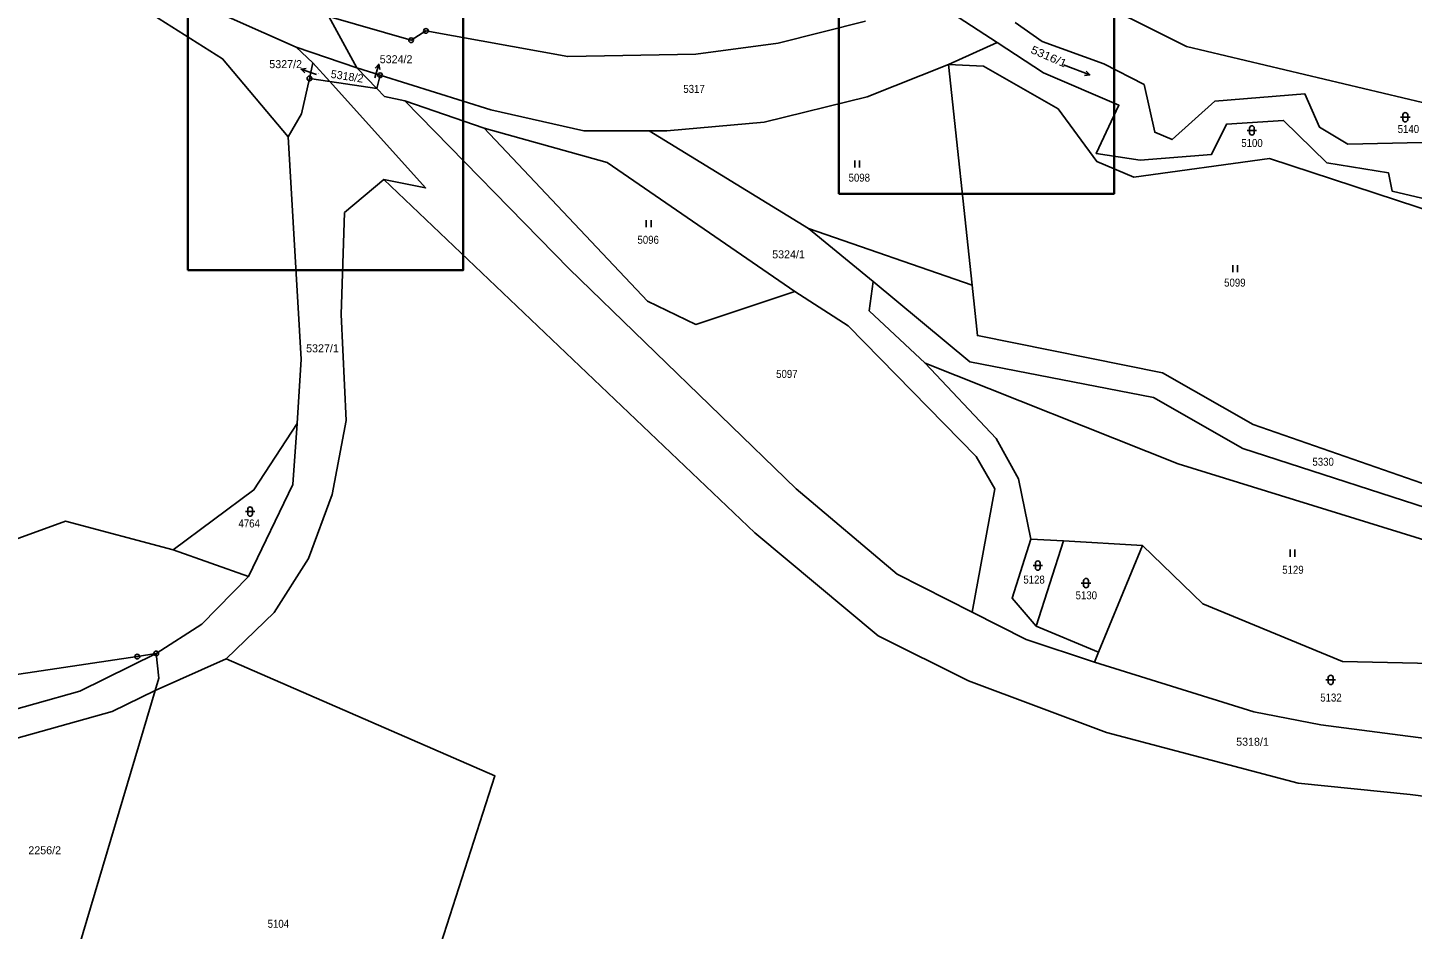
# Model space of a CAD drawing. Extents: x -665688 to -664583, y -1006118 to -1004927.
# Drawn here: x -665191.6 to -664897.5, y -1005645.6 to -1005454.1 of the extents above; entities that cross this region are included whole.
import ezdxf
from ezdxf.enums import TextEntityAlignment as Align

# ---------------------------------------------------------------- set-up
doc = ezdxf.new("R2010")
doc.units = 0
doc.header["$LTSCALE"] = 0.68
for name, color, linetype, lineweight in [('1', 7, 'Continuous', 25), ('13', 7, 'Continuous', 25), ('16', 7, 'Continuous', 25), ('24', 7, 'Continuous', 25), ('25', 7, 'Continuous', 25), ('55', 7, 'Continuous', 35)]:
    doc.layers.add(name, color=color, linetype=linetype, lineweight=lineweight)
doc.layers.add('18', color=7, linetype='Continuous')

msp = doc.modelspace()

# ---------------------------------------------------------------- linework, layer by layer
at = {"layer": '1'}
for p, q in [((-665000.67, -1005447.45), (-664985.67, -1005457.24)), ((-665094.68, -1005475.42), (-665111.5, -1005469.59)), ((-665012.03, -1005508), (-665025.73, -1005496.73)), ((-664978.49, -1005562.71), (-664971.54, -1005563.1)), ((-664971.54, -1005563.1), (-664954.79, -1005564.05)), ((-665164.55, -1005594.86), (-665149.48, -1005588.12))]:
    msp.add_line(p, q, dxfattribs=at)
for points in [[(-665399.75, -1005208.35), (-665376.11, -1005222.26), (-665358.6, -1005232.91), (-665344.4, -1005243.08), (-665327.83, -1005258.99), (-665299.41, -1005297.42), (-665287.03, -1005311.31), (-665268.55, -1005328.24), (-665251.87, -1005341.72), (-665211.4, -1005376.84), (-665190.33, -1005399.99), (-665148.79, -1005443.19), (-665127.68, -1005451.74), (-665121.7, -1005462.65), (-665134.58, -1005458.21)], [(-665136.29, -1005477.24), (-665150.22, -1005460.69), (-665177.15, -1005443.61), (-665221.19, -1005409.78), (-665210.58, -1005407.96)], [(-665210.58, -1005407.96), (-665198.15, -1005420.12), (-665184.6, -1005432.15), (-665168.91, -1005442.94), (-665134.58, -1005458.21), (-665131.02, -1005461.53)], [(-665013.61, -1005452.67), (-665032.2, -1005457.35), (-665049.69, -1005459.74), (-665076.88, -1005460.21), (-665107.01, -1005454.78), (-665110.17, -1005456.74), (-665127.68, -1005451.74), (-665156.4, -1005419.5)], [(-664969.3, -1005446.1), (-664945.43, -1005458.11), (-664870.22, -1005475.95), (-664843.38, -1005478.52), (-664808.84, -1005489.57), (-664807.3, -1005497.72)], [(-664807.3, -1005497.72), (-664823.52, -1005498.49), (-664831.43, -1005490.72), (-664845.63, -1005484.35), (-664861.39, -1005491.91), (-664864, -1005488.5), (-664869.71, -1005485.89), (-664886.34, -1005486.35), (-664888.54, -1005481.42), (-664895.39, -1005478.51), (-664911.15, -1005478.85), (-664917.14, -1005475.22), (-664920.29, -1005468.16), (-664939.44, -1005469.7), (-664948.5, -1005477.86), (-664952.19, -1005476.3), (-664954.45, -1005466.18), (-664962.99, -1005461.77), (-664976.12, -1005457.02), (-664981.8, -1005452.97)], [(-664865, -1005502.46), (-664927.78, -1005481.87), (-664956.61, -1005485.82), (-664964.51, -1005482.49), (-664972.73, -1005471.31), (-664988.54, -1005462.23), (-664995.99, -1005461.94), (-664985.67, -1005457.24)], [(-664985.67, -1005457.24), (-664975.78, -1005463.7), (-664959.79, -1005470.57), (-664964.6, -1005480.83), (-664955.25, -1005482.24), (-664940.12, -1005481), (-664936.96, -1005474.59), (-664924.8, -1005473.77), (-664915.63, -1005482.78), (-664902.52, -1005484.91), (-664901.73, -1005488.82), (-664891.82, -1005491.12), (-664879.66, -1005491.54), (-664869.11, -1005493.1), (-664863.59, -1005498.93)], [(-665131.02, -1005461.53), (-665131.77, -1005464.88), (-665133.46, -1005472.4), (-665136.29, -1005477.24)], [(-665131.77, -1005464.88), (-665127.42, -1005465.53), (-665117.45, -1005467.03), (-665116.75, -1005464.2)], [(-665131.02, -1005461.53), (-665127.42, -1005465.53), (-665107.11, -1005488.12), (-665116, -1005486.34)], [(-665111.5, -1005469.59), (-665115.85, -1005468.68), (-665117.45, -1005467.03), (-665121.7, -1005462.65)], [(-665059.59, -1005476.02), (-665073.49, -1005475.99), (-665093.25, -1005471.56), (-665116.75, -1005464.2), (-665121.7, -1005462.65)], [(-664995.99, -1005461.94), (-665013.28, -1005468.79), (-665035.15, -1005474.13), (-665055.81, -1005476.03), (-665059.59, -1005476.02)], [(-664995.99, -1005461.94), (-664990.99, -1005508.78), (-665025.73, -1005496.73), (-665059.59, -1005476.02)], [(-665111.5, -1005469.59), (-665076.57, -1005505.28), (-665028.39, -1005552.03), (-665006.89, -1005570.2), (-664990.98, -1005578.23)], [(-665094.68, -1005475.42), (-665068.5, -1005482.71), (-665028.64, -1005510.12)], [(-665028.64, -1005510.12), (-665049.69, -1005517.11), (-665059.98, -1005512.21), (-665094.68, -1005475.42)], [(-665136.29, -1005477.24), (-665133.54, -1005524.48), (-665134.36, -1005538.17)], [(-665149.48, -1005588.12), (-665139.26, -1005578.32), (-665131.97, -1005566.85), (-665126.96, -1005553.24), (-665123.96, -1005537.54), (-665125, -1005515), (-665124.35, -1005493.36), (-665116, -1005486.34)], [(-665116, -1005486.34), (-665037.17, -1005561.39), (-665010.92, -1005583.28), (-664991.78, -1005592.85), (-664962.41, -1005603.78), (-664921.71, -1005614.59), (-664897.94, -1005616.96), (-664870.69, -1005620.43), (-664799.26, -1005639.02), (-664782.09, -1005645.9)], [(-665012.03, -1005508), (-665012.84, -1005514.23), (-665000.93, -1005525.33)], [(-664809.58, -1005552.27), (-664838.4, -1005554.75), (-664857.53, -1005560.23), (-664887.07, -1005558.49), (-664933.48, -1005543.45), (-664952.44, -1005532.63), (-664991.45, -1005525.08), (-665012.03, -1005508)], [(-664990.98, -1005578.23), (-664986.14, -1005552.03), (-664990.1, -1005545.19), (-665017.31, -1005517.41), (-665028.64, -1005510.12)], [(-664990.99, -1005508.78), (-664989.85, -1005519.48), (-664950.5, -1005527.4), (-664931.25, -1005538.39), (-664885.68, -1005554.21)], [(-664875.12, -1005565.84), (-664893.9, -1005563.22), (-664947.17, -1005546.75), (-665000.93, -1005525.33)], [(-665000.93, -1005525.33), (-664985.9, -1005541.37), (-664981.09, -1005549.92), (-664978.49, -1005562.71)], [(-665134.36, -1005538.17), (-665135.27, -1005551.09), (-665144.74, -1005570.67), (-665160.74, -1005564.98)], [(-665160.74, -1005564.98), (-665143.58, -1005552.28), (-665134.36, -1005538.17)], [(-665160.74, -1005564.98), (-665183.63, -1005558.92), (-665201.39, -1005565.33), (-665216.34, -1005567.05), (-665244.55, -1005559.36), (-665293.31, -1005561.66), (-665350.23, -1005557.59), (-665359.92, -1005604.3), (-665351.13, -1005608.21)], [(-664977.35, -1005581.18), (-664982.49, -1005575.25), (-664978.49, -1005562.71)], [(-664964.12, -1005586.74), (-664977.35, -1005581.18), (-664971.54, -1005563.1)], [(-664867.38, -1005608.64), (-664916.88, -1005602.2), (-664931.13, -1005599.43), (-664964.98, -1005588.84), (-664964.12, -1005586.74), (-664954.79, -1005564.05)], [(-664954.79, -1005564.05), (-664941.98, -1005576.5), (-664912.3, -1005588.7), (-664870.82, -1005589.64), (-664867.38, -1005608.64)], [(-665144.74, -1005570.67), (-665154.61, -1005580.79), (-665164.31, -1005587.01)], [(-664964.98, -1005588.84), (-664979.49, -1005584.03), (-664990.98, -1005578.23)], [(-665164.55, -1005594.86), (-665163.78, -1005592.26), (-665164.31, -1005587.01), (-665168.34, -1005587.68), (-665243.35, -1005598.85), (-665296.45, -1005604.83), (-665308.45, -1005606.17)], [(-665308.45, -1005606.17), (-665284.38, -1005604.35), (-665226.56, -1005603.1), (-665199.77, -1005600.41), (-665180.59, -1005595.05), (-665164.31, -1005587.01)], [(-665149.48, -1005588.12), (-665092.38, -1005613.01), (-665119.12, -1005696.24)]]:
    msp.add_lwpolyline(points, dxfattribs=at)
at = {"layer": '13'}
for p, q in [((-665164.55, -1005594.86), (-665184.65, -1005662.51)), ((-665173.67, -1005599.35), (-665164.55, -1005594.86)), ((-665198.65, -1005606.34), (-665173.67, -1005599.35))]:
    msp.add_line(p, q, dxfattribs=at)
at = {"layer": '16'}
for p, q in [((-665130.72, -1005463.88), (-665133.546, -1005462.874)), ((-665130.26, -1005464.04), (-665130.72, -1005463.88)), ((-665117.86, -1005464.72), (-665117.029, -1005461.838))]:
    msp.add_line(p, q, dxfattribs=at)
for points in [[(-665132.771, -1005463.681), (-665133.546, -1005462.874), (-665132.436, -1005462.739)], [(-665117.786, -1005462.66), (-665117.029, -1005461.838), (-665116.825, -1005462.938)]]:
    msp.add_lwpolyline(points, dxfattribs=at)
at = {"layer": '24'}
for centre, radius in [((-665107.01, -1005454.78), 0.5), ((-665107.01, -1005454.78), 0.032), ((-665110.17, -1005456.74), 0.5), ((-665110.17, -1005456.74), 0.032), ((-665116.75, -1005464.2), 0.5), ((-665116.75, -1005464.2), 0.032), ((-665131.77, -1005464.88), 0.5), ((-665131.77, -1005464.88), 0.032), ((-665168.34, -1005587.68), 0.5), ((-665168.34, -1005587.68), 0.032), ((-665164.31, -1005587.01), 0.5), ((-665164.31, -1005587.01), 0.032)]:
    msp.add_circle(centre, radius, dxfattribs=at)
at = {"layer": '25'}
for p, q in [((-664971.585, -1005461.951), (-664965.995, -1005464.129)), ((-664899.44, -1005473.61), (-664899.44, -1005472.61)), ((-664898.44, -1005472.61), (-664898.44, -1005473.61)), ((-664932.53, -1005475.92), (-664930.53, -1005475.92)), ((-664932.03, -1005476.42), (-664932.03, -1005475.42)), ((-664931.03, -1005475.42), (-664931.03, -1005476.42)), ((-664899.94, -1005473.11), (-664897.94, -1005473.11)), ((-665015.907, -1005483.815), (-665015.907, -1005482.315)), ((-665014.873, -1005483.815), (-665014.873, -1005482.315)), ((-665060.207, -1005496.465), (-665060.207, -1005494.965)), ((-665059.173, -1005496.465), (-665059.173, -1005494.965)), ((-664935.617, -1005506.045), (-664935.617, -1005504.545)), ((-664934.583, -1005506.045), (-664934.583, -1005504.545)), ((-665145.39, -1005556.88), (-665143.39, -1005556.88)), ((-665144.89, -1005557.38), (-665144.89, -1005556.38)), ((-665143.89, -1005556.38), (-665143.89, -1005557.38)), ((-664923.427, -1005566.455), (-664923.427, -1005564.955)), ((-664922.393, -1005566.455), (-664922.393, -1005564.955)), ((-664978.03, -1005568.34), (-664976.03, -1005568.34)), ((-664977.53, -1005568.84), (-664977.53, -1005567.84)), ((-664976.53, -1005567.84), (-664976.53, -1005568.84)), ((-664967.78, -1005572.07), (-664965.78, -1005572.07)), ((-664967.28, -1005572.57), (-664967.28, -1005571.57)), ((-664966.28, -1005571.57), (-664966.28, -1005572.57)), ((-664915.8, -1005592.62), (-664913.8, -1005592.62)), ((-664915.3, -1005593.12), (-664915.3, -1005592.12)), ((-664914.3, -1005592.12), (-664914.3, -1005593.12))]:
    msp.add_line(p, q, dxfattribs=at)
msp.add_lwpolyline([(-664966.745, -1005463.3), (-664965.995, -1005464.129), (-664967.109, -1005464.232)], dxfattribs=at)
for centre, start, end in [((-664898.94, -1005472.61), 0.101, 180.00143), ((-664931.53, -1005475.42), 0.101, 180.00143), ((-664898.94, -1005473.61), 180.10243, 0.00286), ((-664931.53, -1005476.42), 180.10243, 0.00286), ((-665144.39, -1005556.38), 0.101, 180.00143), ((-665144.39, -1005557.38), 180.10243, 0.00286), ((-664977.03, -1005567.84), 0.101, 180.00143), ((-664977.03, -1005568.84), 180.10243, 0.00286), ((-664966.78, -1005571.57), 0.101, 180.00143), ((-664966.78, -1005572.57), 180.10243, 0.00286), ((-664914.8, -1005592.12), 0.101, 180.00143), ((-664914.8, -1005593.12), 180.10243, 0.00286)]:
    msp.add_arc(centre, 0.5, start, end, dxfattribs=at)
at = {"layer": '55'}
for points in [[(-665019.3, -1005489.36), (-665019.3, -1005403.26), (-664960.8, -1005403.26), (-664960.8, -1005489.36)], [(-665157.63, -1005505.61), (-665157.63, -1005419.51), (-665099.13, -1005419.51), (-665099.13, -1005505.61)]]:
    msp.add_lwpolyline(points, close=True, dxfattribs=at)

# ---------------------------------------------------------------- texts
at = {"layer": '16'}
msp.add_text('5327/2', height=1.7, dxfattribs=at).set_placement((-665133.35, -1005462.68), align=Align.RIGHT)
msp.add_text('5324/2', height=1.7, dxfattribs=at).set_placement((-665116.84, -1005461.64))
at = {"layer": '18', "width": 1.15}
msp.add_text('5316/1', height=1.7, rotation=336.603, dxfattribs=at).set_placement((-664975.014, -1005460.9791), align=Align.CENTER)
at = {"layer": '18'}
for s, height, p in [('5327/2', 0.1, (-665130.06, -1005463.84)), ('5324/2', 0.1, (-665117.66, -1005464.52)), ('5324/1', 1.7, (-665033.46, -1005503.08)), ('5327/1', 1.7, (-665132.48, -1005523.04)), ('5318/1', 1.7, (-664934.88, -1005606.61))]:
    msp.add_text(s, height=height, dxfattribs=at).set_placement(p)
msp.add_text('5318/2', height=1.7, rotation=351.303, dxfattribs=at).set_placement((-665127.333, -1005464.723))
at = {"layer": '18', "width": 0.9}
for s, p in [('5317', (-665050.0595, -1005467.94)), ('5140', (-664898.2895, -1005476.46)), ('5100', (-664931.5195, -1005479.43)), ('5098', (-665014.9495, -1005486.79)), ('5096', (-665059.7995, -1005499.99)), ('5099', (-664935.1595, -1005509.09)), ('5097', (-665030.3395, -1005528.48)), ('5330', (-664916.3995, -1005547.14)), ('4764', (-665144.5795, -1005560.24)), ('5129', (-664922.8195, -1005570.08)), ('5128', (-664977.8195, -1005572.17)), ('5130', (-664966.7195, -1005575.51)), ('5132', (-664914.7395, -1005597.23)), ('5104', (-665138.3795, -1005645.28))]:
    msp.add_text(s, height=1.7, dxfattribs=at).set_placement(p, align=Align.CENTER)
at = {"layer": '18'}
msp.add_text('2256/2', height=1.7, dxfattribs=at).set_placement((-665188.0195, -1005629.67), align=Align.CENTER)

doc.saveas('drawing.dxf')
